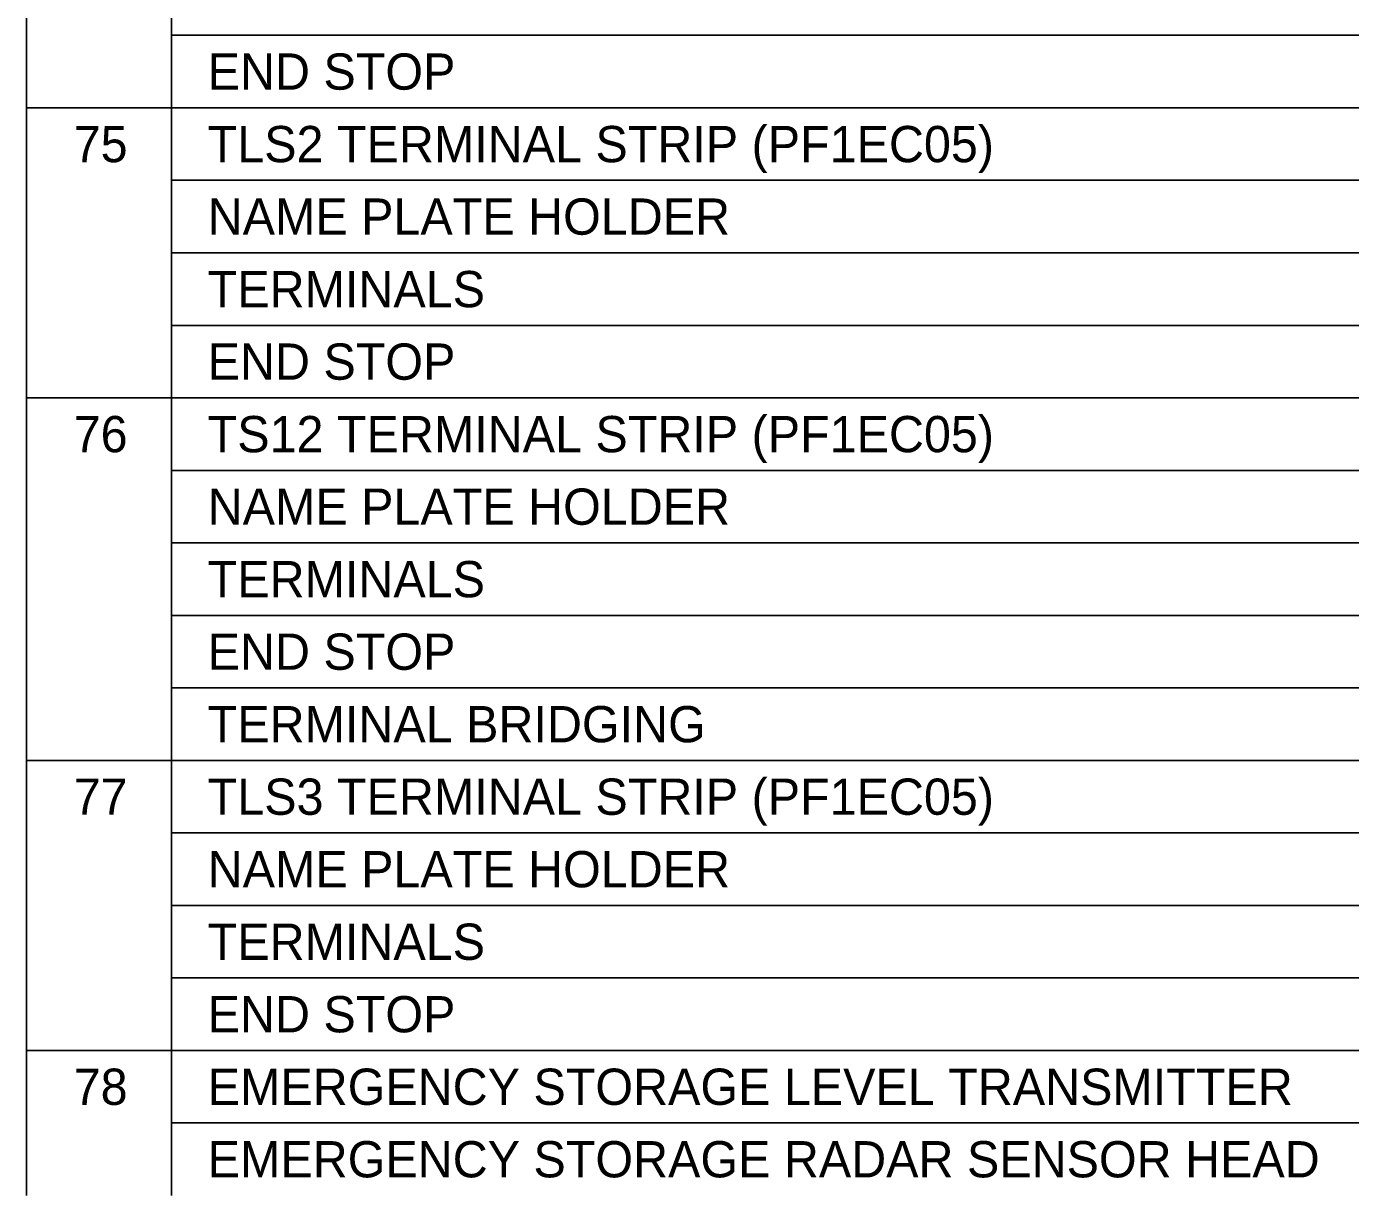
# Model space of a CAD drawing. Extents: x 841 to 1682, y 0 to 594.
# Drawn here: x 1340 to 1431.3, y 75 to 155.6 of the extents above; entities that cross this region are included whole.
import ezdxf

# ---------------------------------------------------------------- set-up
doc = ezdxf.new("R2010")
doc.units = 0
for name, color, linetype in [('BASE', 7, 'Continuous'), ('Default', 7, 'Continuous'), ('Level 1', 7, 'Continuous')]:
    doc.layers.add(name, color=color, linetype=linetype)

msp = doc.modelspace()

# ---------------------------------------------------------------- linework, layer by layer
at = {"layer": 'Default'}
msp.add_line((1350, 80), (1540, 80), dxfattribs=at)
at = {"layer": 'Level 1'}
for p, q in [((1340, 568.5), (1340, 75)), ((1350, 558.75), (1350, 75)), ((1350, 155), (1540, 155)), ((1340, 150), (1540, 150)), ((1350, 145), (1540, 145)), ((1350, 140), (1540, 140)), ((1350, 135), (1540, 135)), ((1340, 130), (1540, 130)), ((1350, 125), (1540, 125)), ((1350, 120), (1540, 120)), ((1350, 115), (1540, 115)), ((1350, 110), (1540, 110)), ((1340, 105), (1540, 105)), ((1350, 100), (1540, 100)), ((1350, 95), (1540, 95)), ((1350, 90), (1540, 90)), ((1340, 85), (1540, 85))]:
    msp.add_line(p, q, dxfattribs=at)

# ---------------------------------------------------------------- texts
at = {"layer": 'BASE'}
for s, p in [('EMERGENCY STORAGE LEVEL TRANSMITTER', (1352.5, 81.25)), ('EMERGENCY STORAGE RADAR SENSOR HEAD', (1352.5, 76.25))]:
    msp.add_text(s, height=2.5, dxfattribs=at).set_placement(p)
at = {"layer": 'Level 1'}
for s, p in [('END STOP', (1352.5, 151.25)), ('75', (1343.257, 146.25)), ('TLS2 TERMINAL STRIP (PF1EC05)', (1352.5, 146.25)), ('NAME PLATE HOLDER', (1352.5, 141.25)), ('TERMINALS', (1352.5, 136.25)), ('END STOP', (1352.5, 131.25)), ('TS12 TERMINAL STRIP (PF1EC05)', (1352.5, 126.25)), ('76', (1343.257, 126.25)), ('NAME PLATE HOLDER', (1352.5, 121.25)), ('TERMINALS', (1352.5, 116.25)), ('END STOP', (1352.5, 111.25)), ('TERMINAL BRIDGING', (1352.5, 106.25)), ('77', (1343.257, 101.25)), ('TLS3 TERMINAL STRIP (PF1EC05)', (1352.5, 101.25)), ('NAME PLATE HOLDER', (1352.5, 96.25)), ('TERMINALS', (1352.5, 91.25)), ('END STOP', (1352.5, 86.25)), ('78', (1343.257, 81.25))]:
    msp.add_text(s, height=2.5, dxfattribs=at).set_placement(p)

doc.saveas('drawing.dxf')
